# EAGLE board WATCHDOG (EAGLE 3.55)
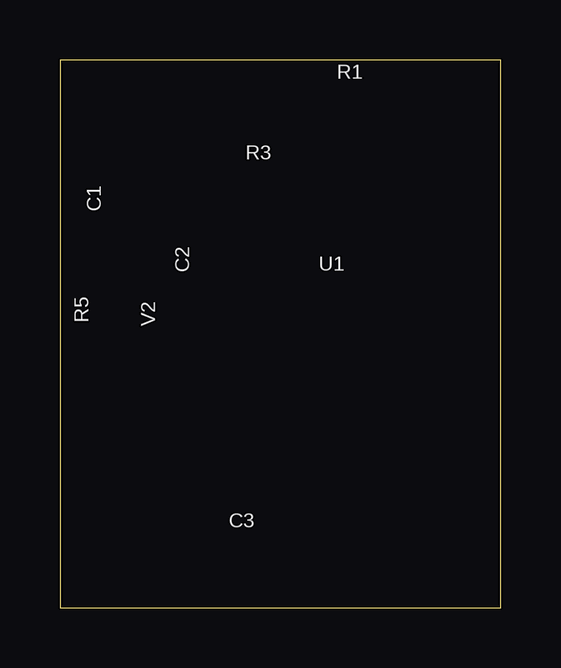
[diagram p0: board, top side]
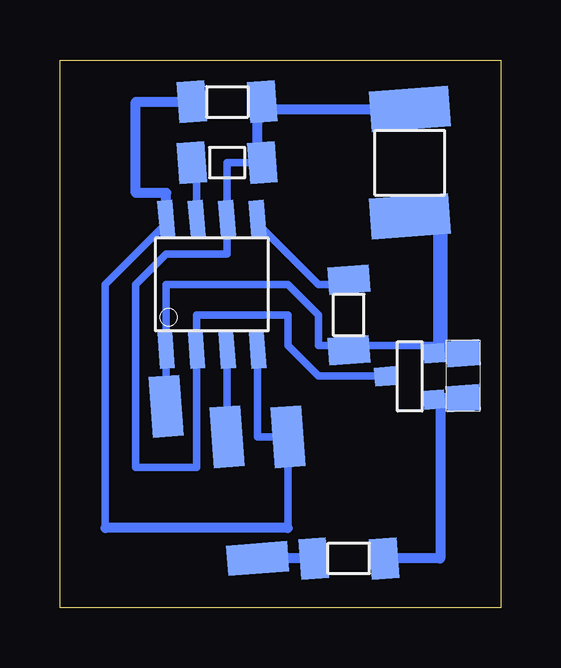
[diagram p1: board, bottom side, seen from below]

Size 18.39 x 22.85 mm. Coordinates in mm from the lower left corner, seen from the top.
Outline: 0,0 18.39,0 18.39,22.85 0,22.85 0,0
Copper layers used: Bottom

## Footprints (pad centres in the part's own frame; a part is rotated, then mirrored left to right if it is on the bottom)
D2 = smd 1.27 x 2.54 rotated 4.3:  0,0
12 = smd 1.702 x 3.302 rotated 4.4:  2.235,0 | smd 1.702 x 3.302 rotated 4.3:  -2.235,0
06 = smd 1.143 x 1.702 rotated 4.4:  1.473,0 | smd 1.143 x 1.702 rotated 4.3:  -1.473,0
05 = smd 1.092 x 1.397 rotated 4.4:  0.94,0 | smd 1.092 x 1.397 rotated 4.3:  -0.94,0
-8 = smd 0.61 x 1.524 rotated 4.3:  -1.27,-2.743 | smd 0.61 x 1.524 rotated 4.9:  -1.27,2.743 | smd 0.61 x 1.524 rotated 4.4:  0,-2.743 | smd 0.61 x 1.524 rotated 4.5:  1.27,-2.743 | smd 0.61 x 1.524 rotated 4.8:  0,2.743 | smd 0.61 x 1.524 rotated 4.7:  1.27,2.743;  2.54,2.743 | smd 0.61 x 1.524 rotated 4.6:  2.54,-2.743
T-23 = smd 0.787 x 0.889 rotated 4.4:  0.991,1.016 | smd 0.787 x 0.889 rotated 4.3:  -0.94,1.016 | smd 0.787 x 0.889 rotated 4.5:  0.025,-1.016

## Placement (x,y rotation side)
+5V  VCC  [D2]  8.88,7.14 180 bottom
C1  10uF  [12]  3.8,18.57 90 bottom
C2  100nF  [06]  6.34,12.22 90 bottom
C3  1uF  [06]  6.34,2.06 180 bottom
PAD2  Trigger  [D2]  10.16,2.06 270 bottom
PAD4  GND  [D2]  13.96,8.41 0 bottom
R1  1M  [06]  11.43,21.11 0 bottom
R3  10k  [06]  11.43,18.57 0 bottom
R5  100k  [05]  1.58,9.68 270 bottom
RESET  OUT  [D2]  11.43,7.14 0 bottom
U1  555N  [-8]  12.7,13.49 0 bottom
V2  BC817S23  [T-23]  3.8,9.68 270 bottom

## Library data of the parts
+5V PAD2 PAD4 RESET = WIREPAD
C1-C3 R1 U1 V2 = micon
R3 = DISCRETE
R5 = pdc

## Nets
N$1: +5V. R1. U1.
N$2: C2. U1.
N$4: R3. U1.
N$5: C1. C2. PAD4. R5. U1. V2.
N$9: RESET. U1.
N$10: C3. PAD2.
N$11: C3. R5. V2.
N$12: C1. R1. R3. U1. V2.

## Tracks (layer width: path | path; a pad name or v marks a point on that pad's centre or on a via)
N$1
  Bottom 0.305: 10.16,10.95 10.16,10.74 10.16,7.14 +5V. 8.88,3.33 | 13.96,16.03 16.5,13.49 16.5,3.33
  Bottom 0.406: R1. 15.24,21.11 15.24,17.3 13.96,17.3 13.96,16.03 13.96,16.23 | 8.88,3.33 16.5,3.33
N$2
  Bottom 0.305: U1. 10.16,16.03 7.61,13.49 6.34,13.49 6.34,13.69
N$4
  Bottom 0.305: 12.7,16.03 12.7,16.23 12.7,18.57 R3.
N$5
  Bottom 0.305: PAD4. 13.96,10.74 13.96,13.49 8.88,13.49 7.61,12.22 7.61,10.95 6.34,10.95 | 6.34,10.95 2.54,10.95 2.79,10.62 | 2.54,16.03 C1. | 6.34,10.95 C2.
  Bottom 0.406: 2.85,10.62 2.79,10.62 | R5. 2.85,10.62 | 2.85,10.62 2.85,10.63
  Bottom 0.61: 2.54,10.95 2.54,16.03
N$9
  Bottom 0.305: 11.43,10.95 11.43,10.74 RESET.
N$10
  Bottom 0.406: 7.82,2.06 7.61,2.06 7.93,2.06 PAD2.
N$11
  Bottom 0.305: 2.54,8.41 2.79,8.69
  Bottom 0.406: 5.08,2.06 C3. 2.54,2.06 2.54,8.41 2.54,8.74 1.58,8.74
N$12
  Bottom 0.305: 10.16,18.57 11.43,18.57 11.43,16.23 11.43,14.76 13.96,14.76 15.24,13.49 15.24,5.87 12.7,5.87 12.7,10.74 12.7,12.22 8.88,12.22 8.88,10.95 7.61,9.68 5.08,9.68 V2.
  Bottom 0.406: 3.8,20.8 10.16,20.8 10.16,21.11 | 9.95,18.57 10.16,18.57 10.16,21.11 | 10.16,21.11 9.95,21.11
